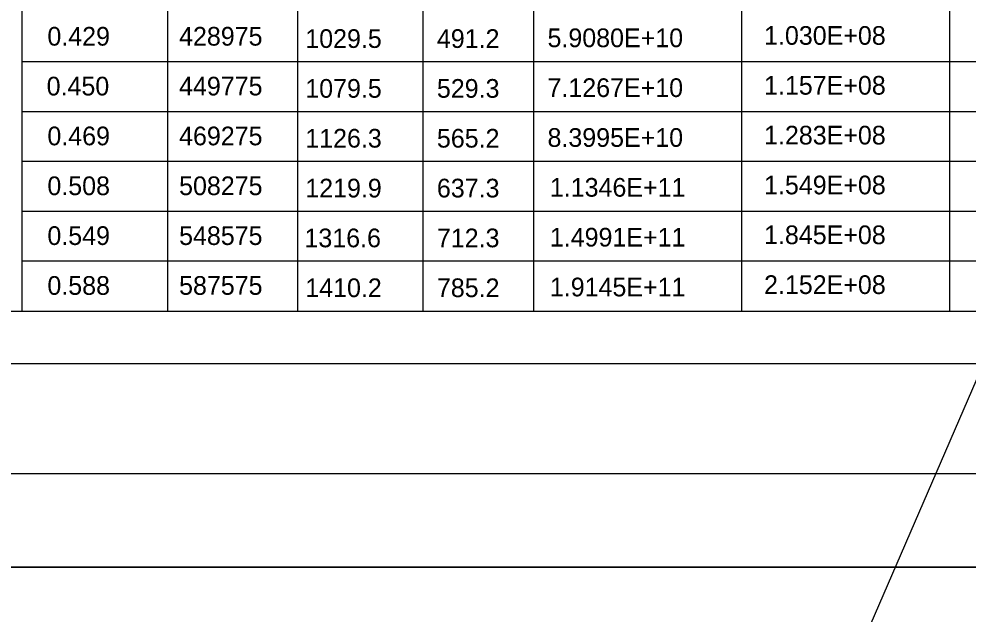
# Model space of a CAD drawing. Extents: x 635698 to 639877, y 296617 to 300175.
# Drawn here: x 636902.1 to 637054.4, y 299463.3 to 299558.8 of the extents above; entities that cross this region are included whole.
import ezdxf

# ---------------------------------------------------------------- set-up
doc = ezdxf.new("R2010")
doc.units = 0
for name, color, linetype in [('1', 7, 'Continuous'), ('2', 7, 'Continuous'), ('PLT-BNDY', 7, 'Continuous')]:
    doc.layers.add(name, color=color, linetype=linetype)

msp = doc.modelspace()

# ---------------------------------------------------------------- linework, layer by layer
at = {"layer": '1'}
msp.add_line((637313.22, 300096.11), (636518.29, 298258.33), dxfattribs=at)
at = {"layer": '2'}
for p, q in [((636902.58, 299646.25), (636902.58, 299511.88)), ((636925.95, 299634.38), (636925.95, 299511.88)), ((636946.83, 299634.38), (636946.83, 299511.88)), ((636966.95, 299634.38), (636966.95, 299511.88)), ((636984.7, 299634.38), (636984.7, 299511.88)), ((637018.08, 299634.38), (637018.08, 299511.88)), ((637051.45, 299634.38), (637051.45, 299511.88)), ((637084.83, 299551.88), (636902.58, 299551.88)), ((637084.83, 299543.88), (636902.58, 299543.88)), ((637084.83, 299535.88), (636902.58, 299535.88)), ((637084.83, 299527.88), (636902.58, 299527.88)), ((637084.83, 299519.88), (636902.58, 299519.88)), ((636700.95, 299511.88), (637084.83, 299511.88)), ((636556.08, 299503.46), (637093.43, 299503.46)), ((637331.45, 299485.76), (636545.45, 299485.76))]:
    msp.add_line(p, q, dxfattribs=at)
at = {"layer": 'PLT-BNDY'}
for points in [[(636505.45, 300064.76), (637346.45, 300064.76), (637346.45, 299470.76), (636505.45, 299470.76)], [(636505.45, 299470.76), (637346.45, 299470.76), (637346.45, 298876.76), (636505.45, 298876.76)]]:
    msp.add_lwpolyline(points, close=True, dxfattribs=at)

# ---------------------------------------------------------------- texts
at = {"layer": '2'}
for s, p in [('0.429', (636906.7, 299554.5)), ('428975', (636927.83, 299554.5)), ('1029.5', (636948.08, 299554.13)), ('491.2', (636969.2, 299554.13)), ('5.9080E+10', (636986.95, 299554.25)), ('1.030E+08', (637021.7, 299554.63)), ('0.450', (636906.58, 299546.5)), ('449775', (636927.83, 299546.5)), ('1079.5', (636948.08, 299546.13)), ('529.3', (636969.2, 299546.13)), ('7.1267E+10', (636986.95, 299546.25)), ('1.157E+08', (637021.7, 299546.63)), ('0.469', (636906.7, 299538.5)), ('469275', (636927.83, 299538.5)), ('1.283E+08', (637021.7, 299538.63)), ('1126.3', (636948.08, 299538.13)), ('565.2', (636969.2, 299538.13)), ('8.3995E+10', (636986.95, 299538.25)), ('0.508', (636906.7, 299530.5)), ('508275', (636927.83, 299530.5)), ('1219.9', (636948.08, 299530.13)), ('637.3', (636969.2, 299530.13)), ('1.1346E+11', (636987.33, 299530.25)), ('1.549E+08', (637021.7, 299530.63)), ('0.549', (636906.7, 299522.5)), ('548575', (636927.83, 299522.5)), ('1316.6', (636947.95, 299522.13)), ('712.3', (636969.2, 299522.13)), ('1.4991E+11', (636987.33, 299522.25)), ('1.845E+08', (637021.7, 299522.63)), ('0.588', (636906.7, 299514.5)), ('587575', (636927.83, 299514.5)), ('1410.2', (636948.08, 299514.13)), ('785.2', (636969.2, 299514.13)), ('1.9145E+11', (636987.33, 299514.25)), ('2.152E+08', (637021.7, 299514.63))]:
    msp.add_text(s, height=3, dxfattribs=at).set_placement(p)

doc.saveas('drawing.dxf')
